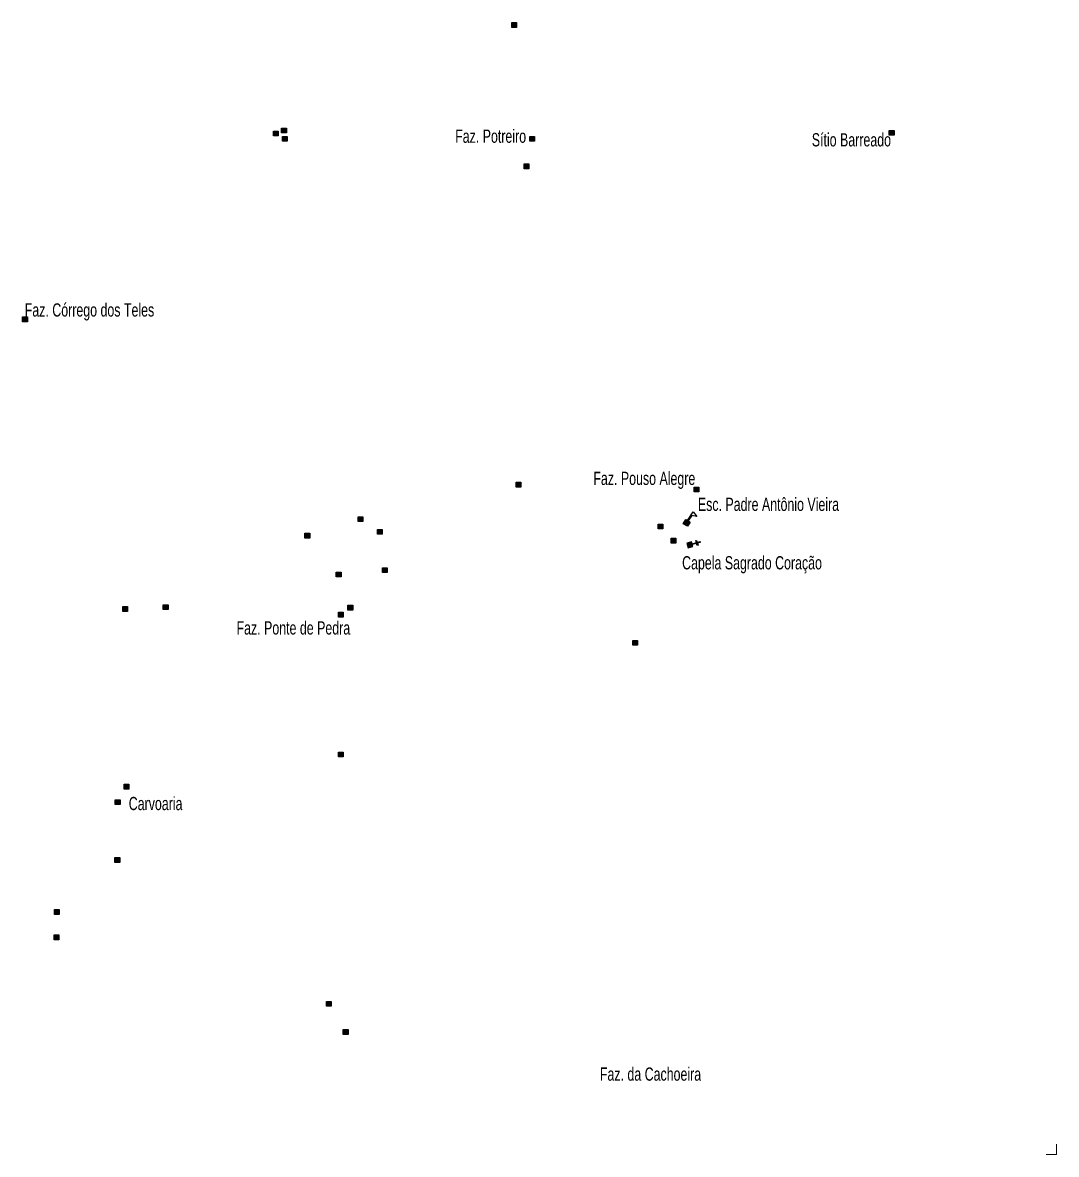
# Model space of a CAD drawing. Extents: x 447.8 to 473.9, y 7733.1 to 7760.8.
# Drawn here: x 467.68 to 473.93, y 7733.14 to 7739.98 of the extents above; entities that cross this region are included whole.
import ezdxf
from ezdxf.enums import TextEntityAlignment as Align

# ---------------------------------------------------------------- set-up
doc = ezdxf.new("R2010")
doc.units = 0
doc.header["$LTSCALE"] = 0.032
for name, color, linetype, lineweight in [('2', 7, 'Continuous', 25), ('4', 7, 'Continuous', 25), ('6', 7, 'Continuous', 25), ('63', 7, 'Continuous', 13)]:
    doc.layers.add(name, color=color, linetype=linetype, lineweight=lineweight)
doc.layers.add('61', color=7, linetype='Continuous')

msp = doc.modelspace()

# ---------------------------------------------------------------- hatches: boundary and pattern name
at = {"layer": '2'}
for points in [[(470.6377, 7739.9838), (470.6667, 7739.9838), (470.6667, 7739.9548), (470.6377, 7739.9548)], [(469.1978, 7739.3278), (469.2268, 7739.3278), (469.2268, 7739.2988), (469.1978, 7739.2988)], [(469.2468, 7739.347), (469.2758, 7739.347), (469.2758, 7739.318), (469.2468, 7739.318)], [(472.9189, 7739.3321), (472.9479, 7739.3321), (472.9479, 7739.3031), (472.9189, 7739.3031)], [(469.2511, 7739.2959), (469.2801, 7739.2959), (469.2801, 7739.2669), (469.2511, 7739.2669)], [(470.7463, 7739.2959), (470.7753, 7739.2959), (470.7753, 7739.2669), (470.7463, 7739.2669)], [(470.7122, 7739.1297), (470.7412, 7739.1297), (470.7412, 7739.1007), (470.7122, 7739.1007)], [(467.6816, 7738.2055), (467.7106, 7738.2055), (467.7106, 7738.1765), (467.6816, 7738.1765)], [(470.6633, 7737.2064), (470.6923, 7737.2064), (470.6923, 7737.1774), (470.6633, 7737.1774)], [(471.7389, 7737.1766), (471.7679, 7737.1766), (471.7679, 7737.1476), (471.7389, 7737.1476)], [(469.709, 7736.9976), (469.738, 7736.9976), (469.738, 7736.9686), (469.709, 7736.9686)], [(469.8262, 7736.921), (469.8552, 7736.921), (469.8552, 7736.892), (469.8262, 7736.892)], [(471.5216, 7736.9529), (471.5506, 7736.9529), (471.5506, 7736.9239), (471.5216, 7736.9239)], [(469.3874, 7736.8975), (469.4164, 7736.8975), (469.4164, 7736.8685), (469.3874, 7736.8685)], [(471.6004, 7736.8677), (471.6294, 7736.8677), (471.6294, 7736.8387), (471.6004, 7736.8387)], [(469.577, 7736.6632), (469.606, 7736.6632), (469.606, 7736.6342), (469.577, 7736.6342)], [(469.856, 7736.6888), (469.885, 7736.6888), (469.885, 7736.6598), (469.856, 7736.6598)], [(468.2862, 7736.4545), (468.3152, 7736.4545), (468.3152, 7736.4255), (468.2862, 7736.4255)], [(468.5312, 7736.4652), (468.5602, 7736.4652), (468.5602, 7736.4362), (468.5312, 7736.4362)], [(469.6473, 7736.463), (469.6763, 7736.463), (469.6763, 7736.434), (469.6473, 7736.434)], [(469.5898, 7736.4204), (469.6188, 7736.4204), (469.6188, 7736.3914), (469.5898, 7736.3914)], [(471.3683, 7736.25), (471.3973, 7736.25), (471.3973, 7736.221), (471.3683, 7736.221)], [(469.5898, 7735.5748), (469.6188, 7735.5748), (469.6188, 7735.5458), (469.5898, 7735.5458)], [(468.2947, 7735.381), (468.3237, 7735.381), (468.3237, 7735.352), (468.2947, 7735.352)], [(468.2415, 7735.2873), (468.2705, 7735.2873), (468.2705, 7735.2583), (468.2415, 7735.2583)], [(468.2394, 7734.938), (468.2684, 7734.938), (468.2684, 7734.909), (468.2394, 7734.909)], [(467.8739, 7734.6234), (467.9029, 7734.6234), (467.9029, 7734.5944), (467.8739, 7734.5944)], [(467.8716, 7734.4701), (467.9006, 7734.4701), (467.9006, 7734.4411), (467.8716, 7734.4411)], [(469.5173, 7734.069), (469.5463, 7734.069), (469.5463, 7734.04), (469.5173, 7734.04)], [(469.6196, 7733.8986), (469.6486, 7733.8986), (469.6486, 7733.8696), (469.6196, 7733.8696)]]:
    msp.add_hatch(color=256, dxfattribs=at).paths.add_polyline_path(points)
at = {"layer": '4'}
msp.add_hatch(color=256, dxfattribs=at).paths.add_polyline_path([(471.6739, 7736.9558), (471.6896, 7736.9813), (471.7151, 7736.9656), (471.6994, 7736.9401)])
at = {"layer": '6'}
for points in [[(471.7236, 7736.846), (471.6947, 7736.8378), (471.703, 7736.809), (471.7318, 7736.8172)], [(471.7284, 7736.8292), (471.727, 7736.834), (471.7535, 7736.8416), (471.75, 7736.8536), (471.7548, 7736.855), (471.7583, 7736.8429), (471.7751, 7736.8477), (471.7765, 7736.8429), (471.7596, 7736.8381), (471.7631, 7736.8261), (471.7583, 7736.8247), (471.7548, 7736.8368)]]:
    msp.add_hatch(color=256, dxfattribs=at).paths.add_polyline_path(points)

# ---------------------------------------------------------------- linework, layer by layer
at = {"layer": '2'}
for points in [[(470.6377, 7739.9838), (470.6667, 7739.9838), (470.6667, 7739.9548), (470.6377, 7739.9548)], [(469.1978, 7739.3278), (469.2268, 7739.3278), (469.2268, 7739.2988), (469.1978, 7739.2988)], [(469.2468, 7739.347), (469.2758, 7739.347), (469.2758, 7739.318), (469.2468, 7739.318)], [(472.9189, 7739.3321), (472.9479, 7739.3321), (472.9479, 7739.3031), (472.9189, 7739.3031)], [(469.2511, 7739.2959), (469.2801, 7739.2959), (469.2801, 7739.2669), (469.2511, 7739.2669)], [(470.7463, 7739.2959), (470.7753, 7739.2959), (470.7753, 7739.2669), (470.7463, 7739.2669)], [(470.7122, 7739.1297), (470.7412, 7739.1297), (470.7412, 7739.1007), (470.7122, 7739.1007)], [(467.6816, 7738.2055), (467.7106, 7738.2055), (467.7106, 7738.1765), (467.6816, 7738.1765)], [(470.6633, 7737.2064), (470.6923, 7737.2064), (470.6923, 7737.1774), (470.6633, 7737.1774)], [(471.7389, 7737.1766), (471.7679, 7737.1766), (471.7679, 7737.1476), (471.7389, 7737.1476)], [(469.709, 7736.9976), (469.738, 7736.9976), (469.738, 7736.9686), (469.709, 7736.9686)], [(469.8262, 7736.921), (469.8552, 7736.921), (469.8552, 7736.892), (469.8262, 7736.892)], [(471.5216, 7736.9529), (471.5506, 7736.9529), (471.5506, 7736.9239), (471.5216, 7736.9239)], [(469.3874, 7736.8975), (469.4164, 7736.8975), (469.4164, 7736.8685), (469.3874, 7736.8685)], [(471.6004, 7736.8677), (471.6294, 7736.8677), (471.6294, 7736.8387), (471.6004, 7736.8387)], [(469.577, 7736.6632), (469.606, 7736.6632), (469.606, 7736.6342), (469.577, 7736.6342)], [(469.856, 7736.6888), (469.885, 7736.6888), (469.885, 7736.6598), (469.856, 7736.6598)], [(468.2862, 7736.4545), (468.3152, 7736.4545), (468.3152, 7736.4255), (468.2862, 7736.4255)], [(468.5312, 7736.4652), (468.5602, 7736.4652), (468.5602, 7736.4362), (468.5312, 7736.4362)], [(469.6473, 7736.463), (469.6763, 7736.463), (469.6763, 7736.434), (469.6473, 7736.434)], [(469.5898, 7736.4204), (469.6188, 7736.4204), (469.6188, 7736.3914), (469.5898, 7736.3914)], [(471.3683, 7736.25), (471.3973, 7736.25), (471.3973, 7736.221), (471.3683, 7736.221)], [(469.5898, 7735.5748), (469.6188, 7735.5748), (469.6188, 7735.5458), (469.5898, 7735.5458)], [(468.2947, 7735.381), (468.3237, 7735.381), (468.3237, 7735.352), (468.2947, 7735.352)], [(468.2415, 7735.2873), (468.2705, 7735.2873), (468.2705, 7735.2583), (468.2415, 7735.2583)], [(468.2394, 7734.938), (468.2684, 7734.938), (468.2684, 7734.909), (468.2394, 7734.909)], [(467.8739, 7734.6234), (467.9029, 7734.6234), (467.9029, 7734.5944), (467.8739, 7734.5944)], [(467.8716, 7734.4701), (467.9006, 7734.4701), (467.9006, 7734.4411), (467.8716, 7734.4411)], [(469.5173, 7734.069), (469.5463, 7734.069), (469.5463, 7734.04), (469.5173, 7734.04)], [(469.6196, 7733.8986), (469.6486, 7733.8986), (469.6486, 7733.8696), (469.6196, 7733.8696)]]:
    msp.add_lwpolyline(points, close=True, dxfattribs=at)
at = {"layer": '4'}
msp.add_line((471.7002, 7736.9748), (471.7045, 7736.9722), dxfattribs=at)
for points in [[(471.6739, 7736.9558), (471.6896, 7736.9813), (471.7151, 7736.9656), (471.6994, 7736.9401)], [(471.7002, 7736.9748), (471.733, 7737.028), (471.7563, 7736.999), (471.7252, 7737.0058), (471.7045, 7736.9722)]]:
    msp.add_lwpolyline(points, close=True, dxfattribs=at)
at = {"layer": '6'}
for points in [[(471.7236, 7736.846), (471.6947, 7736.8378), (471.703, 7736.809), (471.7318, 7736.8172)], [(471.7284, 7736.8292), (471.727, 7736.834), (471.7535, 7736.8416), (471.75, 7736.8536), (471.7548, 7736.855), (471.7583, 7736.8429), (471.7751, 7736.8477), (471.7765, 7736.8429), (471.7596, 7736.8381), (471.7631, 7736.8261), (471.7583, 7736.8247), (471.7548, 7736.8368)]]:
    msp.add_lwpolyline(points, close=True, dxfattribs=at)
at = {"layer": '63'}
msp.add_lwpolyline([(473.867, 7733.1443), (473.9286, 7733.1443), (473.9286, 7733.205)], dxfattribs=at)

# ---------------------------------------------------------------- texts
at = {"layer": '61', "width": 0.7}
for s, p in [('Faz. Potreiro', (470.7241, 7739.2575)), ('Sítio Barreado', (472.9293, 7739.2357)), ('Faz. Pouso Alegre', (471.7466, 7737.1898)), ('Faz. Ponte de Pedra', (469.661, 7736.2857))]:
    msp.add_text(s, height=0.08, dxfattribs=at).set_placement(p, align=Align.RIGHT)
for s, p in [('Faz. Córrego dos Teles', (467.6944, 7738.2074)), ('Esc. Padre Antônio Vieira', (471.7623, 7737.0327)), ('Capela Sagrado Coração', (471.6669, 7736.6795)), ('Carvoaria', (468.3229, 7735.2246)), ('Faz. da Cachoeira', (471.1701, 7733.5895))]:
    msp.add_text(s, height=0.08, dxfattribs=at).set_placement(p)

doc.saveas('drawing.dxf')
